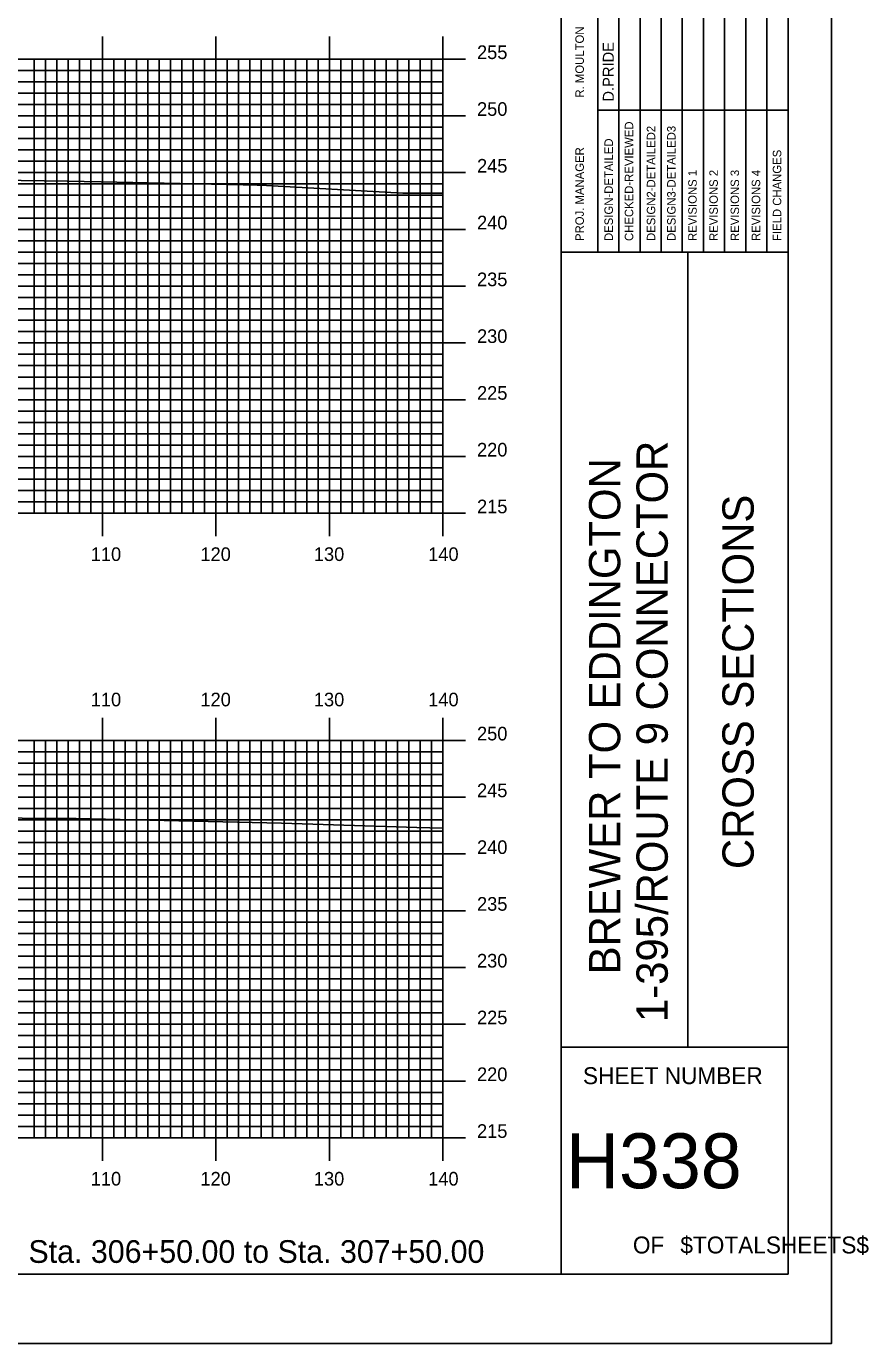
# Model space of a CAD drawing. Extents: x 1817276 to 1817620, y 442591 to 442811.
# Drawn here: x 1817545.4 to 1817619.6, y 442590.5 to 442706.6 of the extents above; entities that cross this region are included whole.
import ezdxf

# ---------------------------------------------------------------- set-up
doc = ezdxf.new("R2010")
doc.units = 0
for name, color, linetype in [('BORDER', 7, 'Continuous'), ('H_V ANNOTATION', 7, 'Continuous'), ('MAJOR', 7, 'Continuous'), ('MINOR', 7, 'Continuous'), ('PLOT BOUNDARY', 7, 'Continuous'), ('S_Roadway_Centerline', 7, 'Continuous')]:
    doc.layers.add(name, color=color, linetype=linetype)

msp = doc.modelspace()

# ---------------------------------------------------------------- linework, layer by layer
at = {"layer": 'BORDER'}
for p, q in [((1817592.5, 442596.67), (1817592.5, 442806.67)), ((1817592.5, 442686.67), (1817612.5, 442686.67)), ((1817603.68, 442616.67), (1817603.68, 442686.67)), ((1817592.5, 442616.67), (1817612.5, 442616.67))]:
    msp.add_line(p, q, dxfattribs=at)
msp.add_lwpolyline([(1817292.5, 442596.67), (1817612.5, 442596.67), (1817612.5, 442806.67), (1817292.5, 442806.67)], close=True, dxfattribs=at)
for points in [[(1817597.59, 442686.68), (1817597.59, 442721.67)], [(1817599.46, 442721.67), (1817599.46, 442686.68)], [(1817601.32, 442686.68), (1817601.32, 442721.67)], [(1817603.18, 442686.68), (1817603.18, 442721.67)], [(1817605.05, 442686.68), (1817605.05, 442721.67)], [(1817606.91, 442686.68), (1817606.91, 442721.67)], [(1817608.77, 442686.68), (1817608.77, 442721.67)], [(1817610.64, 442686.68), (1817610.64, 442721.67)], [(1817595.73, 442686.68), (1817595.73, 442720.26)], [(1817595.73, 442699.17), (1817612.5, 442699.17)]]:
    msp.add_lwpolyline(points, dxfattribs=at)
at = {"layer": 'MAJOR'}
for p, q in [((1817552.1, 442705.67), (1817552.1, 442703.67)), ((1817562.1, 442705.67), (1817562.1, 442703.67)), ((1817572.1, 442705.67), (1817572.1, 442703.67)), ((1817582.1, 442705.67), (1817582.1, 442703.67)), ((1817302.1, 442703.67), (1817582.1, 442703.67)), ((1817302.1, 442703.67), (1817582.1, 442703.67)), ((1817552.1, 442663.67), (1817552.1, 442703.67)), ((1817562.1, 442663.67), (1817562.1, 442703.67)), ((1817572.1, 442663.67), (1817572.1, 442703.67)), ((1817584.1, 442703.67), (1817580.1, 442703.67)), ((1817582.1, 442663.67), (1817582.1, 442703.67)), ((1817582.1, 442663.67), (1817582.1, 442703.67)), ((1817302.1, 442698.67), (1817582.1, 442698.67)), ((1817584.1, 442698.67), (1817580.1, 442698.67)), ((1817302.1, 442693.67), (1817582.1, 442693.67)), ((1817584.1, 442693.67), (1817580.1, 442693.67)), ((1817302.1, 442688.67), (1817582.1, 442688.67)), ((1817584.1, 442688.67), (1817580.1, 442688.67)), ((1817302.1, 442683.67), (1817582.1, 442683.67)), ((1817584.1, 442683.67), (1817580.1, 442683.67)), ((1817302.1, 442678.67), (1817582.1, 442678.67)), ((1817584.1, 442678.67), (1817580.1, 442678.67)), ((1817302.1, 442673.67), (1817582.1, 442673.67)), ((1817584.1, 442673.67), (1817580.1, 442673.67)), ((1817302.1, 442668.67), (1817582.1, 442668.67)), ((1817584.1, 442668.67), (1817580.1, 442668.67)), ((1817302.1, 442663.67), (1817582.1, 442663.67)), ((1817302.1, 442663.67), (1817582.1, 442663.67)), ((1817552.1, 442661.66), (1817552.1, 442663.67)), ((1817562.1, 442661.66), (1817562.1, 442663.67)), ((1817572.1, 442661.66), (1817572.1, 442663.67)), ((1817584.1, 442663.67), (1817580.1, 442663.67)), ((1817582.1, 442661.66), (1817582.1, 442663.67)), ((1817552.1, 442645.67), (1817552.1, 442643.67)), ((1817562.1, 442645.67), (1817562.1, 442643.67)), ((1817572.1, 442645.67), (1817572.1, 442643.67)), ((1817582.1, 442645.67), (1817582.1, 442643.67)), ((1817302.1, 442643.67), (1817582.1, 442643.67)), ((1817302.1, 442643.67), (1817582.1, 442643.67)), ((1817552.1, 442608.67), (1817552.1, 442643.67)), ((1817562.1, 442608.67), (1817562.1, 442643.67)), ((1817572.1, 442608.67), (1817572.1, 442643.67)), ((1817584.1, 442643.67), (1817580.1, 442643.67)), ((1817582.1, 442608.67), (1817582.1, 442643.67)), ((1817582.1, 442608.67), (1817582.1, 442643.67)), ((1817302.1, 442638.67), (1817582.1, 442638.67)), ((1817584.1, 442638.67), (1817580.1, 442638.67)), ((1817302.1, 442633.67), (1817582.1, 442633.67)), ((1817584.1, 442633.67), (1817580.1, 442633.67)), ((1817302.1, 442628.67), (1817582.1, 442628.67)), ((1817584.1, 442628.67), (1817580.1, 442628.67)), ((1817302.1, 442623.67), (1817582.1, 442623.67)), ((1817584.1, 442623.67), (1817580.1, 442623.67)), ((1817302.1, 442618.67), (1817582.1, 442618.67)), ((1817584.1, 442618.67), (1817580.1, 442618.67)), ((1817302.1, 442613.67), (1817582.1, 442613.67)), ((1817584.1, 442613.67), (1817580.1, 442613.67)), ((1817302.1, 442608.67), (1817582.1, 442608.67)), ((1817302.1, 442608.67), (1817582.1, 442608.67)), ((1817552.1, 442606.66), (1817552.1, 442608.67)), ((1817562.1, 442606.66), (1817562.1, 442608.67)), ((1817572.1, 442606.66), (1817572.1, 442608.67)), ((1817584.1, 442608.67), (1817580.1, 442608.67)), ((1817582.1, 442606.66), (1817582.1, 442608.67))]:
    msp.add_line(p, q, dxfattribs=at)
at = {"layer": 'MINOR'}
for p, q in [((1817546.1, 442663.67), (1817546.1, 442703.67)), ((1817547.1, 442663.67), (1817547.1, 442703.67)), ((1817548.1, 442663.67), (1817548.1, 442703.67)), ((1817549.1, 442663.67), (1817549.1, 442703.67)), ((1817550.1, 442663.67), (1817550.1, 442703.67)), ((1817551.1, 442663.67), (1817551.1, 442703.67)), ((1817553.1, 442663.67), (1817553.1, 442703.67)), ((1817554.1, 442663.67), (1817554.1, 442703.67)), ((1817555.1, 442663.67), (1817555.1, 442703.67)), ((1817556.1, 442663.67), (1817556.1, 442703.67)), ((1817557.1, 442663.67), (1817557.1, 442703.67)), ((1817558.1, 442663.67), (1817558.1, 442703.67)), ((1817559.1, 442663.67), (1817559.1, 442703.67)), ((1817560.1, 442663.67), (1817560.1, 442703.67)), ((1817561.1, 442663.67), (1817561.1, 442703.67)), ((1817563.1, 442663.67), (1817563.1, 442703.67)), ((1817564.1, 442663.67), (1817564.1, 442703.67)), ((1817565.1, 442663.67), (1817565.1, 442703.67)), ((1817566.1, 442663.67), (1817566.1, 442703.67)), ((1817567.1, 442663.67), (1817567.1, 442703.67)), ((1817568.1, 442663.67), (1817568.1, 442703.67)), ((1817569.1, 442663.67), (1817569.1, 442703.67)), ((1817570.1, 442663.67), (1817570.1, 442703.67)), ((1817571.1, 442663.67), (1817571.1, 442703.67)), ((1817573.1, 442663.67), (1817573.1, 442703.67)), ((1817574.1, 442663.67), (1817574.1, 442703.67)), ((1817575.1, 442663.67), (1817575.1, 442703.67)), ((1817576.1, 442663.67), (1817576.1, 442703.67)), ((1817577.1, 442663.67), (1817577.1, 442703.67)), ((1817578.1, 442663.67), (1817578.1, 442703.67)), ((1817579.1, 442663.67), (1817579.1, 442703.67)), ((1817580.1, 442663.67), (1817580.1, 442703.67)), ((1817581.1, 442663.67), (1817581.1, 442703.67)), ((1817302.1, 442702.67), (1817582.1, 442702.67)), ((1817582.1, 442702.67), (1817580.1, 442702.67)), ((1817302.1, 442701.67), (1817582.1, 442701.67)), ((1817302.1, 442700.67), (1817582.1, 442700.67)), ((1817582.1, 442701.67), (1817580.1, 442701.67)), ((1817582.1, 442700.67), (1817580.1, 442700.67)), ((1817302.1, 442699.67), (1817582.1, 442699.67)), ((1817582.1, 442699.67), (1817580.1, 442699.67)), ((1817302.1, 442697.67), (1817582.1, 442697.67)), ((1817582.1, 442697.67), (1817580.1, 442697.67)), ((1817302.1, 442696.67), (1817582.1, 442696.67)), ((1817582.1, 442696.67), (1817580.1, 442696.67)), ((1817302.1, 442695.67), (1817582.1, 442695.67)), ((1817582.1, 442695.67), (1817580.1, 442695.67)), ((1817302.1, 442694.67), (1817582.1, 442694.67)), ((1817582.1, 442694.67), (1817580.1, 442694.67)), ((1817302.1, 442692.67), (1817582.1, 442692.67)), ((1817582.1, 442692.67), (1817580.1, 442692.67)), ((1817302.1, 442691.67), (1817582.1, 442691.67)), ((1817582.1, 442691.67), (1817580.1, 442691.67)), ((1817302.1, 442690.67), (1817582.1, 442690.67)), ((1817582.1, 442690.67), (1817580.1, 442690.67)), ((1817302.1, 442689.67), (1817582.1, 442689.67)), ((1817582.1, 442689.67), (1817580.1, 442689.67)), ((1817302.1, 442687.67), (1817582.1, 442687.67)), ((1817582.1, 442687.67), (1817580.1, 442687.67)), ((1817302.1, 442686.67), (1817582.1, 442686.67)), ((1817302.1, 442685.67), (1817582.1, 442685.67)), ((1817582.1, 442686.67), (1817580.1, 442686.67)), ((1817582.1, 442685.67), (1817580.1, 442685.67)), ((1817302.1, 442684.67), (1817582.1, 442684.67)), ((1817582.1, 442684.67), (1817580.1, 442684.67)), ((1817302.1, 442682.67), (1817582.1, 442682.67)), ((1817582.1, 442682.67), (1817580.1, 442682.67)), ((1817302.1, 442681.67), (1817582.1, 442681.67)), ((1817582.1, 442681.67), (1817580.1, 442681.67)), ((1817302.1, 442680.67), (1817582.1, 442680.67)), ((1817582.1, 442680.67), (1817580.1, 442680.67)), ((1817302.1, 442679.67), (1817582.1, 442679.67)), ((1817582.1, 442679.67), (1817580.1, 442679.67)), ((1817302.1, 442677.67), (1817582.1, 442677.67)), ((1817582.1, 442677.67), (1817580.1, 442677.67)), ((1817302.1, 442676.67), (1817582.1, 442676.67)), ((1817582.1, 442676.67), (1817580.1, 442676.67)), ((1817302.1, 442675.67), (1817582.1, 442675.67)), ((1817582.1, 442675.67), (1817580.1, 442675.67)), ((1817302.1, 442674.67), (1817582.1, 442674.67)), ((1817582.1, 442674.67), (1817580.1, 442674.67)), ((1817302.1, 442672.67), (1817582.1, 442672.67)), ((1817302.1, 442671.67), (1817582.1, 442671.67)), ((1817582.1, 442672.67), (1817580.1, 442672.67)), ((1817582.1, 442671.67), (1817580.1, 442671.67)), ((1817302.1, 442670.67), (1817582.1, 442670.67)), ((1817582.1, 442670.67), (1817580.1, 442670.67)), ((1817302.1, 442669.67), (1817582.1, 442669.67)), ((1817582.1, 442669.67), (1817580.1, 442669.67)), ((1817302.1, 442667.67), (1817582.1, 442667.67)), ((1817582.1, 442667.67), (1817580.1, 442667.67)), ((1817302.1, 442666.67), (1817582.1, 442666.67)), ((1817582.1, 442666.67), (1817580.1, 442666.67)), ((1817302.1, 442665.67), (1817582.1, 442665.67)), ((1817302.1, 442664.67), (1817582.1, 442664.67)), ((1817582.1, 442665.67), (1817580.1, 442665.67)), ((1817582.1, 442664.67), (1817580.1, 442664.67)), ((1817302.1, 442642.67), (1817582.1, 442642.67)), ((1817546.1, 442608.67), (1817546.1, 442643.67)), ((1817547.1, 442608.67), (1817547.1, 442643.67)), ((1817548.1, 442608.67), (1817548.1, 442643.67)), ((1817549.1, 442608.67), (1817549.1, 442643.67)), ((1817550.1, 442608.67), (1817550.1, 442643.67)), ((1817551.1, 442608.67), (1817551.1, 442643.67)), ((1817553.1, 442608.67), (1817553.1, 442643.67)), ((1817554.1, 442608.67), (1817554.1, 442643.67)), ((1817555.1, 442608.67), (1817555.1, 442643.67)), ((1817556.1, 442608.67), (1817556.1, 442643.67)), ((1817557.1, 442608.67), (1817557.1, 442643.67)), ((1817558.1, 442608.67), (1817558.1, 442643.67)), ((1817559.1, 442608.67), (1817559.1, 442643.67)), ((1817560.1, 442608.67), (1817560.1, 442643.67)), ((1817561.1, 442608.67), (1817561.1, 442643.67)), ((1817563.1, 442608.67), (1817563.1, 442643.67)), ((1817564.1, 442608.67), (1817564.1, 442643.67)), ((1817565.1, 442608.67), (1817565.1, 442643.67)), ((1817566.1, 442608.67), (1817566.1, 442643.67)), ((1817567.1, 442608.67), (1817567.1, 442643.67)), ((1817568.1, 442608.67), (1817568.1, 442643.67)), ((1817569.1, 442608.67), (1817569.1, 442643.67)), ((1817570.1, 442608.67), (1817570.1, 442643.67)), ((1817571.1, 442608.67), (1817571.1, 442643.67)), ((1817573.1, 442608.67), (1817573.1, 442643.67)), ((1817574.1, 442608.67), (1817574.1, 442643.67)), ((1817575.1, 442608.67), (1817575.1, 442643.67)), ((1817576.1, 442608.67), (1817576.1, 442643.67)), ((1817577.1, 442608.67), (1817577.1, 442643.67)), ((1817578.1, 442608.67), (1817578.1, 442643.67)), ((1817579.1, 442608.67), (1817579.1, 442643.67)), ((1817580.1, 442608.67), (1817580.1, 442643.67)), ((1817582.1, 442642.67), (1817580.1, 442642.67)), ((1817581.1, 442608.67), (1817581.1, 442643.67)), ((1817302.1, 442641.67), (1817582.1, 442641.67)), ((1817582.1, 442641.67), (1817580.1, 442641.67)), ((1817302.1, 442640.67), (1817582.1, 442640.67)), ((1817582.1, 442640.67), (1817580.1, 442640.67)), ((1817302.1, 442639.67), (1817582.1, 442639.67)), ((1817582.1, 442639.67), (1817580.1, 442639.67)), ((1817302.1, 442637.67), (1817582.1, 442637.67)), ((1817582.1, 442637.67), (1817580.1, 442637.67)), ((1817302.1, 442636.67), (1817582.1, 442636.67)), ((1817302.1, 442635.67), (1817582.1, 442635.67)), ((1817582.1, 442636.67), (1817580.1, 442636.67)), ((1817582.1, 442635.67), (1817580.1, 442635.67)), ((1817302.1, 442634.67), (1817582.1, 442634.67)), ((1817582.1, 442634.67), (1817580.1, 442634.67)), ((1817302.1, 442632.67), (1817582.1, 442632.67)), ((1817582.1, 442632.67), (1817580.1, 442632.67)), ((1817302.1, 442631.67), (1817582.1, 442631.67)), ((1817582.1, 442631.67), (1817580.1, 442631.67)), ((1817302.1, 442630.67), (1817582.1, 442630.67)), ((1817582.1, 442630.67), (1817580.1, 442630.67)), ((1817302.1, 442629.67), (1817582.1, 442629.67)), ((1817582.1, 442629.67), (1817580.1, 442629.67)), ((1817302.1, 442627.67), (1817582.1, 442627.67)), ((1817582.1, 442627.67), (1817580.1, 442627.67)), ((1817302.1, 442626.67), (1817582.1, 442626.67)), ((1817582.1, 442626.67), (1817580.1, 442626.67)), ((1817302.1, 442625.67), (1817582.1, 442625.67)), ((1817582.1, 442625.67), (1817580.1, 442625.67)), ((1817302.1, 442624.67), (1817582.1, 442624.67)), ((1817582.1, 442624.67), (1817580.1, 442624.67)), ((1817302.1, 442622.67), (1817582.1, 442622.67)), ((1817582.1, 442622.67), (1817580.1, 442622.67)), ((1817302.1, 442621.67), (1817582.1, 442621.67)), ((1817302.1, 442620.67), (1817582.1, 442620.67)), ((1817582.1, 442621.67), (1817580.1, 442621.67)), ((1817582.1, 442620.67), (1817580.1, 442620.67)), ((1817302.1, 442619.67), (1817582.1, 442619.67)), ((1817582.1, 442619.67), (1817580.1, 442619.67)), ((1817302.1, 442617.67), (1817582.1, 442617.67)), ((1817582.1, 442617.67), (1817580.1, 442617.67)), ((1817302.1, 442616.67), (1817582.1, 442616.67)), ((1817582.1, 442616.67), (1817580.1, 442616.67)), ((1817302.1, 442615.67), (1817582.1, 442615.67)), ((1817582.1, 442615.67), (1817580.1, 442615.67)), ((1817302.1, 442614.67), (1817582.1, 442614.67)), ((1817582.1, 442614.67), (1817580.1, 442614.67)), ((1817302.1, 442612.67), (1817582.1, 442612.67)), ((1817582.1, 442612.67), (1817580.1, 442612.67)), ((1817302.1, 442611.67), (1817582.1, 442611.67)), ((1817582.1, 442611.67), (1817580.1, 442611.67)), ((1817302.1, 442610.67), (1817582.1, 442610.67)), ((1817582.1, 442610.67), (1817580.1, 442610.67)), ((1817302.1, 442609.67), (1817582.1, 442609.67)), ((1817582.1, 442609.67), (1817580.1, 442609.67))]:
    msp.add_line(p, q, dxfattribs=at)
at = {"layer": 'PLOT BOUNDARY'}
msp.add_lwpolyline([(1817276.31, 442590.55), (1817616.31, 442590.55), (1817616.31, 442810.55), (1817276.31, 442810.55)], close=True, dxfattribs=at)
at = {"layer": 'S_Roadway_Centerline'}
for points in [[(1817472.07, 442693.71), (1817481.2, 442693.66), (1817485.38, 442693.56), (1817498.3, 442693.48), (1817500.5, 442693.51), (1817515.15, 442693.81), (1817520.85, 442693.62), (1817532.3, 442693.36), (1817538.85, 442693.07), (1817549.01, 442692.91), (1817551.99, 442692.87), (1817564.51, 442692.59), (1817565.74, 442692.57), (1817566.02, 442692.56), (1817578.57, 442691.87), (1817581.69, 442691.86), (1817582.1, 442691.85)], [(1817467.72, 442637.74), (1817477.24, 442637.99), (1817490.64, 442638.02), (1817494.21, 442638.03), (1817502.31, 442637.69), (1817509.21, 442637.37), (1817511.17, 442637.28), (1817523.44, 442637.21), (1817528.38, 442637.33), (1817536.93, 442637.05), (1817545.03, 442636.83), (1817549.79, 442636.8), (1817567.89, 442636.37), (1817579.8, 442635.99), (1817582.1, 442635.93)]]:
    msp.add_lwpolyline(points, dxfattribs=at)

# ---------------------------------------------------------------- texts
at = {"layer": 'BORDER'}
for s, height, p in [('R. MOULTON', 0.745, (1817594.51, 442700.28)), ('D.PRIDE', 0.969, (1817597.15, 442699.92)), ('CHECKED-REVIEWED', 0.7455, (1817598.86, 442687.65)), ('DESIGN2-DETAILED2', 0.7455, (1817600.8, 442687.65)), ('DESIGN3-DETAILED3', 0.7455, (1817602.59, 442687.65)), ('DESIGN-DETAILED', 0.7455, (1817597.07, 442687.65)), ('PROJ. MANAGER', 0.7455, (1817594.51, 442687.65)), ('FIELD CHANGES', 0.7455, (1817611.9, 442687.65)), ('REVISIONS 1', 0.7455, (1817604.45, 442687.65)), ('REVISIONS 2', 0.7455, (1817606.31, 442687.65)), ('REVISIONS 3', 0.7455, (1817608.18, 442687.65)), ('REVISIONS 4', 0.7455, (1817610.04, 442687.65)), ('1-395/ROUTE 9 CONNECTOR', 2.7557, (1817601.9, 442618.87)), ('BREWER TO EDDINGTON', 2.7557, (1817597.72, 442623.07)), ('CROSS SECTIONS', 2.7557, (1817609.47, 442632.34))]:
    msp.add_text(s, height=height, rotation=90, dxfattribs=at).set_placement(p)
for s, height, p in [('SHEET NUMBER', 1.4905, (1817594.43, 442613.4)), ('H338', 4.839, (1817592.94, 442604.23)), ('OF', 1.491, (1817598.83, 442598.49)), ('$TOTALSHEETS$', 1.4905, (1817603.01, 442598.49))]:
    msp.add_text(s, height=height, dxfattribs=at).set_placement(p)
at = {"layer": 'H_V ANNOTATION'}
for s, height, p in [('255', 1.2, (1817585.1, 442703.67)), ('250', 1.2, (1817585.1, 442698.67)), ('245', 1.2, (1817585.1, 442693.67)), ('240', 1.2, (1817585.1, 442688.67)), ('235', 1.2, (1817585.1, 442683.67)), ('230', 1.2, (1817585.1, 442678.67)), ('225', 1.2, (1817585.1, 442673.67)), ('220', 1.2, (1817585.1, 442668.67)), ('215', 1.2, (1817585.1, 442663.67)), ('110', 1.2, (1817551.08, 442659.47)), ('120', 1.2, (1817560.74, 442659.47)), ('130', 1.2, (1817570.73, 442659.47)), ('140', 1.2, (1817580.8, 442659.47)), ('110', 1.2, (1817551.08, 442646.67)), ('120', 1.2, (1817560.74, 442646.67)), ('130', 1.2, (1817570.73, 442646.67)), ('140', 1.2, (1817580.8, 442646.67)), ('250', 1.2, (1817585.1, 442643.67)), ('245', 1.2, (1817585.1, 442638.67)), ('240', 1.2, (1817585.1, 442633.67)), ('235', 1.2, (1817585.1, 442628.67)), ('230', 1.2, (1817585.1, 442623.67)), ('225', 1.2, (1817585.1, 442618.67)), ('220', 1.2, (1817585.1, 442613.67)), ('215', 1.2, (1817585.1, 442608.67)), ('110', 1.2, (1817551.08, 442604.47)), ('120', 1.2, (1817560.74, 442604.47)), ('130', 1.2, (1817570.73, 442604.47)), ('140', 1.2, (1817580.8, 442604.47)), ('Sta. 306+50.00 to Sta. 307+50.00', 2.0004, (1817545.59, 442597.66))]:
    msp.add_text(s, height=height, dxfattribs=at).set_placement(p)

doc.saveas('drawing.dxf')
